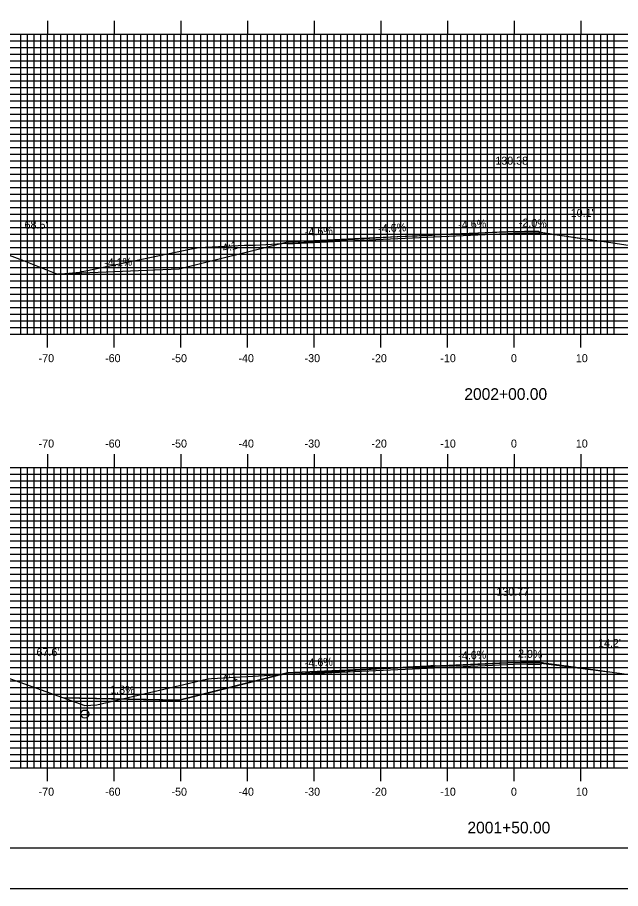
# Model space of a CAD drawing. Extents: x 851139 to 851482, y 366605 to 366825.
# Drawn here: x 851230.4 to 851320.9, y 366604.9 to 366735.5 of the extents above; entities that cross this region are included whole.
import ezdxf

# ---------------------------------------------------------------- set-up
doc = ezdxf.new("R2010")
doc.units = 0
for name, color, linetype in [('ANNOTATION', 7, 'Continuous'), ('BORDER', 7, 'Continuous'), ('D_Roadway_Centerline', 7, 'Continuous'), ('D_Roadway_Centerline_Text', 7, 'Continuous'), ('D_Roadway_Edge_Shoulder', 7, 'Continuous'), ('D_Roadway_Edge_TW', 7, 'Continuous'), ('D_Roadway_SlopeLines', 7, 'Continuous'), ('D_Text_Standard', 7, 'Continuous'), ('H_V ANNOTATION', 7, 'Continuous'), ('M_Roadway_Centerline', 7, 'Continuous'), ('MAJOR', 7, 'Continuous'), ('MINOR', 7, 'Continuous'), ('PLOT BOUNDARY', 7, 'Continuous'), ('S_Drainage_Invert', 7, 'Continuous'), ('S_Roadway_Centerline', 7, 'Continuous')]:
    doc.layers.add(name, color=color, linetype=linetype)

msp = doc.modelspace()

# ---------------------------------------------------------------- linework, layer by layer
at = {"layer": 'BORDER'}
msp.add_lwpolyline([(851155.34, 366611.06), (851475.34, 366611.06), (851475.34, 366821.06), (851155.34, 366821.06)], close=True, dxfattribs=at)
at = {"layer": 'D_Roadway_Centerline'}
for p, q in [((851304.94, 366703.44), (851308.94, 366703.36)), ((851304.94, 366703.19), (851308.94, 366703.11)), ((851304.94, 366638.82), (851308.94, 366638.74)), ((851308.94, 366638.74), (851319.17, 366637.43))]:
    msp.add_line(p, q, dxfattribs=at)
msp.add_lwpolyline([(851237.33, 366633.52), (851251.73, 366633.25), (851254.68, 366633.2), (851254.68, 366633.2), (851262.09, 366635.05), (851270.94, 366637.26), (851280.94, 366637.72), (851280.94, 366637.72), (851292.94, 366638.27), (851298.7, 366638.54), (851304.94, 366638.82), (851304.94, 366638.82), (851308.94, 366638.74), (851319.16, 366637.43)], dxfattribs=at)
at = {"layer": 'D_Roadway_Edge_Shoulder'}
for points in [[(851304.94, 366703.44), (851308.94, 366703.36), (851308.94, 366703.11), (851304.94, 366703.19)], [(851280.94, 366702.33), (851270.94, 366701.87), (851270.94, 366701.62), (851280.94, 366702.08)], [(851280.94, 366637.72), (851270.94, 366637.26), (851270.94, 366637.01), (851280.94, 366637.47)], [(851304.94, 366638.82), (851308.94, 366638.74), (851308.94, 366638.49), (851304.94, 366638.57)]]:
    msp.add_lwpolyline(points, close=True, dxfattribs=at)
at = {"layer": 'D_Roadway_Edge_TW'}
for points in [[(851304.94, 366703.44), (851292.94, 366702.89), (851292.94, 366702.64), (851304.94, 366703.19)], [(851292.94, 366702.89), (851280.94, 366702.33), (851280.94, 366702.08), (851292.94, 366702.64)], [(851292.94, 366638.27), (851280.94, 366637.72), (851280.94, 366637.47), (851292.94, 366638.02)], [(851304.94, 366638.82), (851292.94, 366638.27), (851292.94, 366638.02), (851304.94, 366638.57)]]:
    msp.add_lwpolyline(points, close=True, dxfattribs=at)
at = {"layer": 'D_Roadway_SlopeLines'}
msp.add_line((851308.94, 366703.36), (851315.06, 366702.42), dxfattribs=at)
for points in [[(851270.94, 366701.87), (851254.68, 366697.81)], [(851254.68, 366697.81), (851236.43, 366697.07)], [(851270.94, 366637.26), (851254.68, 366633.2)], [(851254.68, 366633.2), (851237.33, 366633.52)]]:
    msp.add_lwpolyline(points, dxfattribs=at)
at = {"layer": 'MAJOR'}
for p, q in [((851234.94, 366735.06), (851234.94, 366733.06)), ((851244.94, 366735.06), (851244.94, 366733.06)), ((851254.94, 366735.06), (851254.94, 366733.06)), ((851264.94, 366735.06), (851264.94, 366733.06)), ((851274.94, 366735.06), (851274.94, 366733.06)), ((851284.94, 366735.06), (851284.94, 366733.06)), ((851294.94, 366735.06), (851294.94, 366733.06)), ((851304.94, 366735.06), (851304.94, 366733.06)), ((851314.94, 366735.06), (851314.94, 366733.06)), ((851164.94, 366733.06), (851444.94, 366733.06)), ((851164.94, 366733.06), (851444.94, 366733.06)), ((851234.94, 366688.06), (851234.94, 366733.06)), ((851244.94, 366688.06), (851244.94, 366733.06)), ((851254.94, 366688.06), (851254.94, 366733.06)), ((851264.94, 366688.06), (851264.94, 366733.06)), ((851274.94, 366688.06), (851274.94, 366733.06)), ((851284.94, 366688.06), (851284.94, 366733.06)), ((851294.94, 366688.06), (851294.94, 366733.06)), ((851304.94, 366688.06), (851304.94, 366733.06)), ((851314.94, 366688.06), (851314.94, 366733.06)), ((851164.94, 366728.06), (851444.94, 366728.06)), ((851164.94, 366723.06), (851444.94, 366723.06)), ((851164.94, 366718.06), (851444.94, 366718.06)), ((851164.94, 366713.06), (851444.94, 366713.06)), ((851164.94, 366708.06), (851444.94, 366708.06)), ((851164.94, 366703.06), (851444.94, 366703.06)), ((851164.94, 366698.06), (851444.94, 366698.06)), ((851164.94, 366693.06), (851444.94, 366693.06)), ((851164.94, 366688.06), (851444.94, 366688.06)), ((851164.94, 366688.06), (851444.94, 366688.06)), ((851234.94, 366686.05), (851234.94, 366688.06)), ((851244.94, 366686.05), (851244.94, 366688.06)), ((851254.94, 366686.05), (851254.94, 366688.06)), ((851264.94, 366686.05), (851264.94, 366688.06)), ((851274.94, 366686.05), (851274.94, 366688.06)), ((851284.94, 366686.05), (851284.94, 366688.06)), ((851294.94, 366686.05), (851294.94, 366688.06)), ((851304.94, 366686.05), (851304.94, 366688.06)), ((851314.94, 366686.05), (851314.94, 366688.06)), ((851234.94, 366670.06), (851234.94, 366668.06)), ((851244.94, 366670.06), (851244.94, 366668.06)), ((851254.94, 366670.06), (851254.94, 366668.06)), ((851264.94, 366670.06), (851264.94, 366668.06)), ((851274.94, 366670.06), (851274.94, 366668.06)), ((851284.94, 366670.06), (851284.94, 366668.06)), ((851294.94, 366670.06), (851294.94, 366668.06)), ((851304.94, 366670.06), (851304.94, 366668.06)), ((851314.94, 366670.06), (851314.94, 366668.06)), ((851164.94, 366668.06), (851444.94, 366668.06)), ((851164.94, 366668.06), (851444.94, 366668.06)), ((851234.94, 366623.06), (851234.94, 366668.06)), ((851244.94, 366623.06), (851244.94, 366668.06)), ((851254.94, 366623.06), (851254.94, 366668.06)), ((851264.94, 366623.06), (851264.94, 366668.06)), ((851274.94, 366623.06), (851274.94, 366668.06)), ((851284.94, 366623.06), (851284.94, 366668.06)), ((851294.94, 366623.06), (851294.94, 366668.06)), ((851304.94, 366623.06), (851304.94, 366668.06)), ((851314.94, 366623.06), (851314.94, 366668.06)), ((851164.94, 366663.06), (851444.94, 366663.06)), ((851164.94, 366658.06), (851444.94, 366658.06)), ((851164.94, 366653.06), (851444.94, 366653.06)), ((851164.94, 366648.06), (851444.94, 366648.06)), ((851164.94, 366643.06), (851444.94, 366643.06)), ((851164.94, 366638.06), (851444.94, 366638.06)), ((851164.94, 366633.06), (851444.94, 366633.06)), ((851164.94, 366628.06), (851444.94, 366628.06)), ((851164.94, 366623.06), (851444.94, 366623.06)), ((851164.94, 366623.06), (851444.94, 366623.06)), ((851234.94, 366621.05), (851234.94, 366623.06)), ((851244.94, 366621.05), (851244.94, 366623.06)), ((851254.94, 366621.05), (851254.94, 366623.06)), ((851264.94, 366621.05), (851264.94, 366623.06)), ((851274.94, 366621.05), (851274.94, 366623.06)), ((851284.94, 366621.05), (851284.94, 366623.06)), ((851294.94, 366621.05), (851294.94, 366623.06)), ((851304.94, 366621.05), (851304.94, 366623.06)), ((851314.94, 366621.05), (851314.94, 366623.06))]:
    msp.add_line(p, q, dxfattribs=at)
at = {"layer": 'MINOR'}
for p, q in [((851230.94, 366688.06), (851230.94, 366733.06)), ((851231.94, 366688.06), (851231.94, 366733.06)), ((851232.94, 366688.06), (851232.94, 366733.06)), ((851233.94, 366688.06), (851233.94, 366733.06)), ((851235.94, 366688.06), (851235.94, 366733.06)), ((851236.94, 366688.06), (851236.94, 366733.06)), ((851237.94, 366688.06), (851237.94, 366733.06)), ((851238.94, 366688.06), (851238.94, 366733.06)), ((851239.94, 366688.06), (851239.94, 366733.06)), ((851240.94, 366688.06), (851240.94, 366733.06)), ((851241.94, 366688.06), (851241.94, 366733.06)), ((851242.94, 366688.06), (851242.94, 366733.06)), ((851243.94, 366688.06), (851243.94, 366733.06)), ((851245.94, 366688.06), (851245.94, 366733.06)), ((851246.94, 366688.06), (851246.94, 366733.06)), ((851247.94, 366688.06), (851247.94, 366733.06)), ((851248.94, 366688.06), (851248.94, 366733.06)), ((851249.94, 366688.06), (851249.94, 366733.06)), ((851250.94, 366688.06), (851250.94, 366733.06)), ((851251.94, 366688.06), (851251.94, 366733.06)), ((851252.94, 366688.06), (851252.94, 366733.06)), ((851253.94, 366688.06), (851253.94, 366733.06)), ((851255.94, 366688.06), (851255.94, 366733.06)), ((851256.94, 366688.06), (851256.94, 366733.06)), ((851257.94, 366688.06), (851257.94, 366733.06)), ((851258.94, 366688.06), (851258.94, 366733.06)), ((851259.94, 366688.06), (851259.94, 366733.06)), ((851260.94, 366688.06), (851260.94, 366733.06)), ((851261.94, 366688.06), (851261.94, 366733.06)), ((851262.94, 366688.06), (851262.94, 366733.06)), ((851263.94, 366688.06), (851263.94, 366733.06)), ((851265.94, 366688.06), (851265.94, 366733.06)), ((851266.94, 366688.06), (851266.94, 366733.06)), ((851267.94, 366688.06), (851267.94, 366733.06)), ((851268.94, 366688.06), (851268.94, 366733.06)), ((851269.94, 366688.06), (851269.94, 366733.06)), ((851270.94, 366688.06), (851270.94, 366733.06)), ((851271.94, 366688.06), (851271.94, 366733.06)), ((851272.94, 366688.06), (851272.94, 366733.06)), ((851273.94, 366688.06), (851273.94, 366733.06)), ((851275.94, 366688.06), (851275.94, 366733.06)), ((851276.94, 366688.06), (851276.94, 366733.06)), ((851277.94, 366688.06), (851277.94, 366733.06)), ((851278.94, 366688.06), (851278.94, 366733.06)), ((851279.94, 366688.06), (851279.94, 366733.06)), ((851280.94, 366688.06), (851280.94, 366733.06)), ((851281.94, 366688.06), (851281.94, 366733.06)), ((851282.94, 366688.06), (851282.94, 366733.06)), ((851283.94, 366688.06), (851283.94, 366733.06)), ((851285.94, 366688.06), (851285.94, 366733.06)), ((851286.94, 366688.06), (851286.94, 366733.06)), ((851287.94, 366688.06), (851287.94, 366733.06)), ((851288.94, 366688.06), (851288.94, 366733.06)), ((851289.94, 366688.06), (851289.94, 366733.06)), ((851290.94, 366688.06), (851290.94, 366733.06)), ((851291.94, 366688.06), (851291.94, 366733.06)), ((851292.94, 366688.06), (851292.94, 366733.06)), ((851293.94, 366688.06), (851293.94, 366733.06)), ((851295.94, 366688.06), (851295.94, 366733.06)), ((851296.94, 366688.06), (851296.94, 366733.06)), ((851297.94, 366688.06), (851297.94, 366733.06)), ((851298.94, 366688.06), (851298.94, 366733.06)), ((851299.94, 366688.06), (851299.94, 366733.06)), ((851300.94, 366688.06), (851300.94, 366733.06)), ((851301.94, 366688.06), (851301.94, 366733.06)), ((851302.94, 366688.06), (851302.94, 366733.06)), ((851303.94, 366688.06), (851303.94, 366733.06)), ((851305.94, 366688.06), (851305.94, 366733.06)), ((851306.94, 366688.06), (851306.94, 366733.06)), ((851307.94, 366688.06), (851307.94, 366733.06)), ((851308.94, 366688.06), (851308.94, 366733.06)), ((851309.94, 366688.06), (851309.94, 366733.06)), ((851310.94, 366688.06), (851310.94, 366733.06)), ((851311.94, 366688.06), (851311.94, 366733.06)), ((851312.94, 366688.06), (851312.94, 366733.06)), ((851313.94, 366688.06), (851313.94, 366733.06)), ((851315.94, 366688.06), (851315.94, 366733.06)), ((851316.94, 366688.06), (851316.94, 366733.06)), ((851317.94, 366688.06), (851317.94, 366733.06)), ((851318.94, 366688.06), (851318.94, 366733.06)), ((851319.94, 366688.06), (851319.94, 366733.06)), ((851164.94, 366732.06), (851444.94, 366732.06)), ((851164.94, 366731.06), (851444.94, 366731.06)), ((851164.94, 366730.06), (851444.94, 366730.06)), ((851164.94, 366729.06), (851444.94, 366729.06)), ((851164.94, 366727.06), (851444.94, 366727.06)), ((851164.94, 366726.06), (851444.94, 366726.06)), ((851164.94, 366725.06), (851444.94, 366725.06)), ((851164.94, 366724.06), (851444.94, 366724.06)), ((851164.94, 366722.06), (851444.94, 366722.06)), ((851164.94, 366721.06), (851444.94, 366721.06)), ((851164.94, 366720.06), (851444.94, 366720.06)), ((851164.94, 366719.06), (851444.94, 366719.06)), ((851164.94, 366717.06), (851444.94, 366717.06)), ((851164.94, 366716.06), (851444.94, 366716.06)), ((851164.94, 366715.06), (851444.94, 366715.06)), ((851164.94, 366714.06), (851444.94, 366714.06)), ((851164.94, 366712.06), (851444.94, 366712.06)), ((851164.94, 366711.06), (851444.94, 366711.06)), ((851164.94, 366710.06), (851444.94, 366710.06)), ((851164.94, 366709.06), (851444.94, 366709.06)), ((851164.94, 366707.06), (851444.94, 366707.06)), ((851164.94, 366706.06), (851444.94, 366706.06)), ((851164.94, 366705.06), (851444.94, 366705.06)), ((851164.94, 366704.06), (851444.94, 366704.06)), ((851164.94, 366702.06), (851444.94, 366702.06)), ((851164.94, 366701.06), (851444.94, 366701.06)), ((851164.94, 366700.06), (851444.94, 366700.06)), ((851164.94, 366699.06), (851444.94, 366699.06)), ((851164.94, 366697.06), (851444.94, 366697.06)), ((851164.94, 366696.06), (851444.94, 366696.06)), ((851164.94, 366695.06), (851444.94, 366695.06)), ((851164.94, 366694.06), (851444.94, 366694.06)), ((851164.94, 366692.06), (851444.94, 366692.06)), ((851164.94, 366691.06), (851444.94, 366691.06)), ((851164.94, 366690.06), (851444.94, 366690.06)), ((851164.94, 366689.06), (851444.94, 366689.06)), ((851230.94, 366623.06), (851230.94, 366668.06)), ((851231.94, 366623.06), (851231.94, 366668.06)), ((851232.94, 366623.06), (851232.94, 366668.06)), ((851233.94, 366623.06), (851233.94, 366668.06)), ((851235.94, 366623.06), (851235.94, 366668.06)), ((851236.94, 366623.06), (851236.94, 366668.06)), ((851237.94, 366623.06), (851237.94, 366668.06)), ((851238.94, 366623.06), (851238.94, 366668.06)), ((851239.94, 366623.06), (851239.94, 366668.06)), ((851240.94, 366623.06), (851240.94, 366668.06)), ((851241.94, 366623.06), (851241.94, 366668.06)), ((851242.94, 366623.06), (851242.94, 366668.06)), ((851243.94, 366623.06), (851243.94, 366668.06)), ((851245.94, 366623.06), (851245.94, 366668.06)), ((851246.94, 366623.06), (851246.94, 366668.06)), ((851247.94, 366623.06), (851247.94, 366668.06)), ((851248.94, 366623.06), (851248.94, 366668.06)), ((851249.94, 366623.06), (851249.94, 366668.06)), ((851250.94, 366623.06), (851250.94, 366668.06)), ((851251.94, 366623.06), (851251.94, 366668.06)), ((851252.94, 366623.06), (851252.94, 366668.06)), ((851253.94, 366623.06), (851253.94, 366668.06)), ((851255.94, 366623.06), (851255.94, 366668.06)), ((851256.94, 366623.06), (851256.94, 366668.06)), ((851257.94, 366623.06), (851257.94, 366668.06)), ((851258.94, 366623.06), (851258.94, 366668.06)), ((851259.94, 366623.06), (851259.94, 366668.06)), ((851260.94, 366623.06), (851260.94, 366668.06)), ((851261.94, 366623.06), (851261.94, 366668.06)), ((851262.94, 366623.06), (851262.94, 366668.06)), ((851263.94, 366623.06), (851263.94, 366668.06)), ((851265.94, 366623.06), (851265.94, 366668.06)), ((851266.94, 366623.06), (851266.94, 366668.06)), ((851267.94, 366623.06), (851267.94, 366668.06)), ((851268.94, 366623.06), (851268.94, 366668.06)), ((851269.94, 366623.06), (851269.94, 366668.06)), ((851270.94, 366623.06), (851270.94, 366668.06)), ((851271.94, 366623.06), (851271.94, 366668.06)), ((851272.94, 366623.06), (851272.94, 366668.06)), ((851273.94, 366623.06), (851273.94, 366668.06)), ((851275.94, 366623.06), (851275.94, 366668.06)), ((851276.94, 366623.06), (851276.94, 366668.06)), ((851277.94, 366623.06), (851277.94, 366668.06)), ((851278.94, 366623.06), (851278.94, 366668.06)), ((851279.94, 366623.06), (851279.94, 366668.06)), ((851280.94, 366623.06), (851280.94, 366668.06)), ((851281.94, 366623.06), (851281.94, 366668.06)), ((851282.94, 366623.06), (851282.94, 366668.06)), ((851283.94, 366623.06), (851283.94, 366668.06)), ((851285.94, 366623.06), (851285.94, 366668.06)), ((851286.94, 366623.06), (851286.94, 366668.06)), ((851287.94, 366623.06), (851287.94, 366668.06)), ((851288.94, 366623.06), (851288.94, 366668.06)), ((851289.94, 366623.06), (851289.94, 366668.06)), ((851290.94, 366623.06), (851290.94, 366668.06)), ((851291.94, 366623.06), (851291.94, 366668.06)), ((851292.94, 366623.06), (851292.94, 366668.06)), ((851293.94, 366623.06), (851293.94, 366668.06)), ((851295.94, 366623.06), (851295.94, 366668.06)), ((851296.94, 366623.06), (851296.94, 366668.06)), ((851297.94, 366623.06), (851297.94, 366668.06)), ((851298.94, 366623.06), (851298.94, 366668.06)), ((851299.94, 366623.06), (851299.94, 366668.06)), ((851300.94, 366623.06), (851300.94, 366668.06)), ((851301.94, 366623.06), (851301.94, 366668.06)), ((851302.94, 366623.06), (851302.94, 366668.06)), ((851303.94, 366623.06), (851303.94, 366668.06)), ((851305.94, 366623.06), (851305.94, 366668.06)), ((851306.94, 366623.06), (851306.94, 366668.06)), ((851307.94, 366623.06), (851307.94, 366668.06)), ((851308.94, 366623.06), (851308.94, 366668.06)), ((851309.94, 366623.06), (851309.94, 366668.06)), ((851310.94, 366623.06), (851310.94, 366668.06)), ((851311.94, 366623.06), (851311.94, 366668.06)), ((851312.94, 366623.06), (851312.94, 366668.06)), ((851313.94, 366623.06), (851313.94, 366668.06)), ((851315.94, 366623.06), (851315.94, 366668.06)), ((851316.94, 366623.06), (851316.94, 366668.06)), ((851317.94, 366623.06), (851317.94, 366668.06)), ((851318.94, 366623.06), (851318.94, 366668.06)), ((851319.94, 366623.06), (851319.94, 366668.06)), ((851164.94, 366667.06), (851444.94, 366667.06)), ((851164.94, 366666.06), (851444.94, 366666.06)), ((851164.94, 366665.06), (851444.94, 366665.06)), ((851164.94, 366664.06), (851444.94, 366664.06)), ((851164.94, 366662.06), (851444.94, 366662.06)), ((851164.94, 366661.06), (851444.94, 366661.06)), ((851164.94, 366660.06), (851444.94, 366660.06)), ((851164.94, 366659.06), (851444.94, 366659.06)), ((851164.94, 366657.06), (851444.94, 366657.06)), ((851164.94, 366656.06), (851444.94, 366656.06)), ((851164.94, 366655.06), (851444.94, 366655.06)), ((851164.94, 366654.06), (851444.94, 366654.06)), ((851164.94, 366652.06), (851444.94, 366652.06)), ((851164.94, 366651.06), (851444.94, 366651.06)), ((851164.94, 366650.06), (851444.94, 366650.06)), ((851164.94, 366649.06), (851444.94, 366649.06)), ((851164.94, 366647.06), (851444.94, 366647.06)), ((851164.94, 366646.06), (851444.94, 366646.06)), ((851164.94, 366645.06), (851444.94, 366645.06)), ((851164.94, 366644.06), (851444.94, 366644.06)), ((851164.94, 366642.06), (851444.94, 366642.06)), ((851164.94, 366641.06), (851444.94, 366641.06)), ((851164.94, 366640.06), (851444.94, 366640.06)), ((851164.94, 366639.06), (851444.94, 366639.06)), ((851164.94, 366637.06), (851444.94, 366637.06)), ((851164.94, 366636.06), (851444.94, 366636.06)), ((851164.94, 366635.06), (851444.94, 366635.06)), ((851164.94, 366634.06), (851444.94, 366634.06)), ((851164.94, 366632.06), (851444.94, 366632.06)), ((851164.94, 366631.06), (851444.94, 366631.06)), ((851164.94, 366630.06), (851444.94, 366630.06)), ((851164.94, 366629.06), (851444.94, 366629.06)), ((851164.94, 366627.06), (851444.94, 366627.06)), ((851164.94, 366626.06), (851444.94, 366626.06)), ((851164.94, 366625.06), (851444.94, 366625.06)), ((851164.94, 366624.06), (851444.94, 366624.06))]:
    msp.add_line(p, q, dxfattribs=at)
at = {"layer": 'PLOT BOUNDARY'}
msp.add_lwpolyline([(851139.15, 366604.94), (851479.15, 366604.94), (851479.15, 366824.94), (851139.15, 366824.94)], close=True, dxfattribs=at)
at = {"layer": 'S_Drainage_Invert'}
msp.add_circle((851240.55, 366631.11), 0.6, dxfattribs=at)
at = {"layer": 'S_Roadway_Centerline'}
for points in [[(851214.89, 366705.3), (851231.46, 366699.05), (851236.43, 366697.07), (851239.79, 366697.38), (851240.08, 366697.44), (851240.69, 366697.55), (851256.55, 366700.86), (851257.72, 366701.07), (851264.51, 366701.4), (851266.08, 366701.42), (851275.01, 366701.94), (851287.37, 366702.7), (851291.91, 366702.86), (851292.66, 366702.9), (851292.79, 366703.04), (851293.46, 366703.05), (851295.45, 366703.12), (851306.51, 366703.49), (851308.64, 366703.52), (851308.65, 366703.36), (851310.68, 366703.03), (851319.45, 366701.81), (851328.13, 366700.43)], [(851228.13, 366636.82), (851240.53, 366632.37), (851242.36, 366632.48), (851257.12, 366635.93), (851259.02, 366636.39), (851259.1, 366636.4), (851259.57, 366636.42), (851277.19, 366637.45), (851281.15, 366637.69), (851289.77, 366638.21), (851291.87, 366638.33), (851292.99, 366638.41), (851293.05, 366638.27), (851293.84, 366638.31), (851294.91, 366638.34), (851306.96, 366638.91), (851308.72, 366638.93), (851309.37, 366638.77), (851311.69, 366638.49), (851322.88, 366636.91)]]:
    msp.add_lwpolyline(points, dxfattribs=at)

# ---------------------------------------------------------------- texts
at = {"layer": 'ANNOTATION'}
for s, rotation, p in [('-4.6%', 2.6338, (851284.58, 366703.3)), ('-4.6%', 2.6335, (851296.58, 366703.86)), ('-2.0%', 357.7094, (851305.62, 366704.21)), ('-4.6%', 2.6337, (851273.58, 366702.8)), ('4:1', 14.0376, (851261.35, 366700.34)), ('-4.1%', 2.3273, (851243.48, 366698.16)), ('-4.6%', 2.6338, (851296.58, 366639.24)), ('-2.0%', 357.7096, (851304.96, 366639.62)), ('-4.6%', 2.6339, (851273.58, 366638.18)), ('4:1', 14.0372, (851261.35, 366635.72)), ('1.8%', 358.9468, (851244.35, 366634.19))]:
    msp.add_text(s, height=1.2, rotation=rotation, dxfattribs=at).set_placement(p)
at = {"layer": 'D_Roadway_Centerline_Text'}
for s, p in [('130.38', (851302.12, 366713.47)), ('130.77', (851302.27, 366648.85))]:
    msp.add_text(s, height=1.2, dxfattribs=at).set_placement(p)
at = {"layer": 'D_Text_Standard'}
for s, p in [("10.1'", (851313.42, 366705.63)), ("68.5'", (851231.51, 366703.86)), ("14.2'", (851317.52, 366641.15)), ("67.6'", (851233.3, 366639.79))]:
    msp.add_text(s, height=1.2, dxfattribs=at).set_placement(p)
at = {"layer": 'H_V ANNOTATION'}
for s, height, p in [('-70', 1.2, (851233.62, 366683.86)), ('-60', 1.2, (851243.59, 366683.86)), ('-50', 1.2, (851253.55, 366683.86)), ('-40', 1.2, (851263.59, 366683.86)), ('-30', 1.2, (851273.51, 366683.86)), ('-20', 1.2, (851283.53, 366683.86)), ('-10', 1.2, (851293.87, 366683.86)), ('0', 1.2, (851304.46, 366683.86)), ('10', 1.2, (851314.19, 366683.86)), ('2002+00.00', 1.75, (851297.46, 366678.21)), ('-70', 1.2, (851233.62, 366671.06)), ('-60', 1.2, (851243.59, 366671.06)), ('-50', 1.2, (851253.55, 366671.06)), ('-40', 1.2, (851263.59, 366671.06)), ('-30', 1.2, (851273.51, 366671.06)), ('-20', 1.2, (851283.53, 366671.06)), ('-10', 1.2, (851293.87, 366671.06)), ('0', 1.2, (851304.46, 366671.06)), ('10', 1.2, (851314.19, 366671.06)), ('-70', 1.2, (851233.62, 366618.86)), ('-60', 1.2, (851243.59, 366618.86)), ('-50', 1.2, (851253.55, 366618.86)), ('-40', 1.2, (851263.59, 366618.86)), ('-30', 1.2, (851273.51, 366618.86)), ('-20', 1.2, (851283.53, 366618.86)), ('-10', 1.2, (851293.87, 366618.86)), ('0', 1.2, (851304.46, 366618.86)), ('10', 1.2, (851314.19, 366618.86)), ('2001+50.00', 1.75, (851297.93, 366613.21))]:
    msp.add_text(s, height=height, dxfattribs=at).set_placement(p)
at = {"layer": 'M_Roadway_Centerline'}
for s, p in [('C', (851292.78, 366703.04)), ('L', (851292.79, 366703.03)), ('C', (851292.99, 366638.41)), ('L', (851292.99, 366638.41))]:
    msp.add_text(s, height=0.0146, dxfattribs=at).set_placement(p)

doc.saveas('drawing.dxf')
